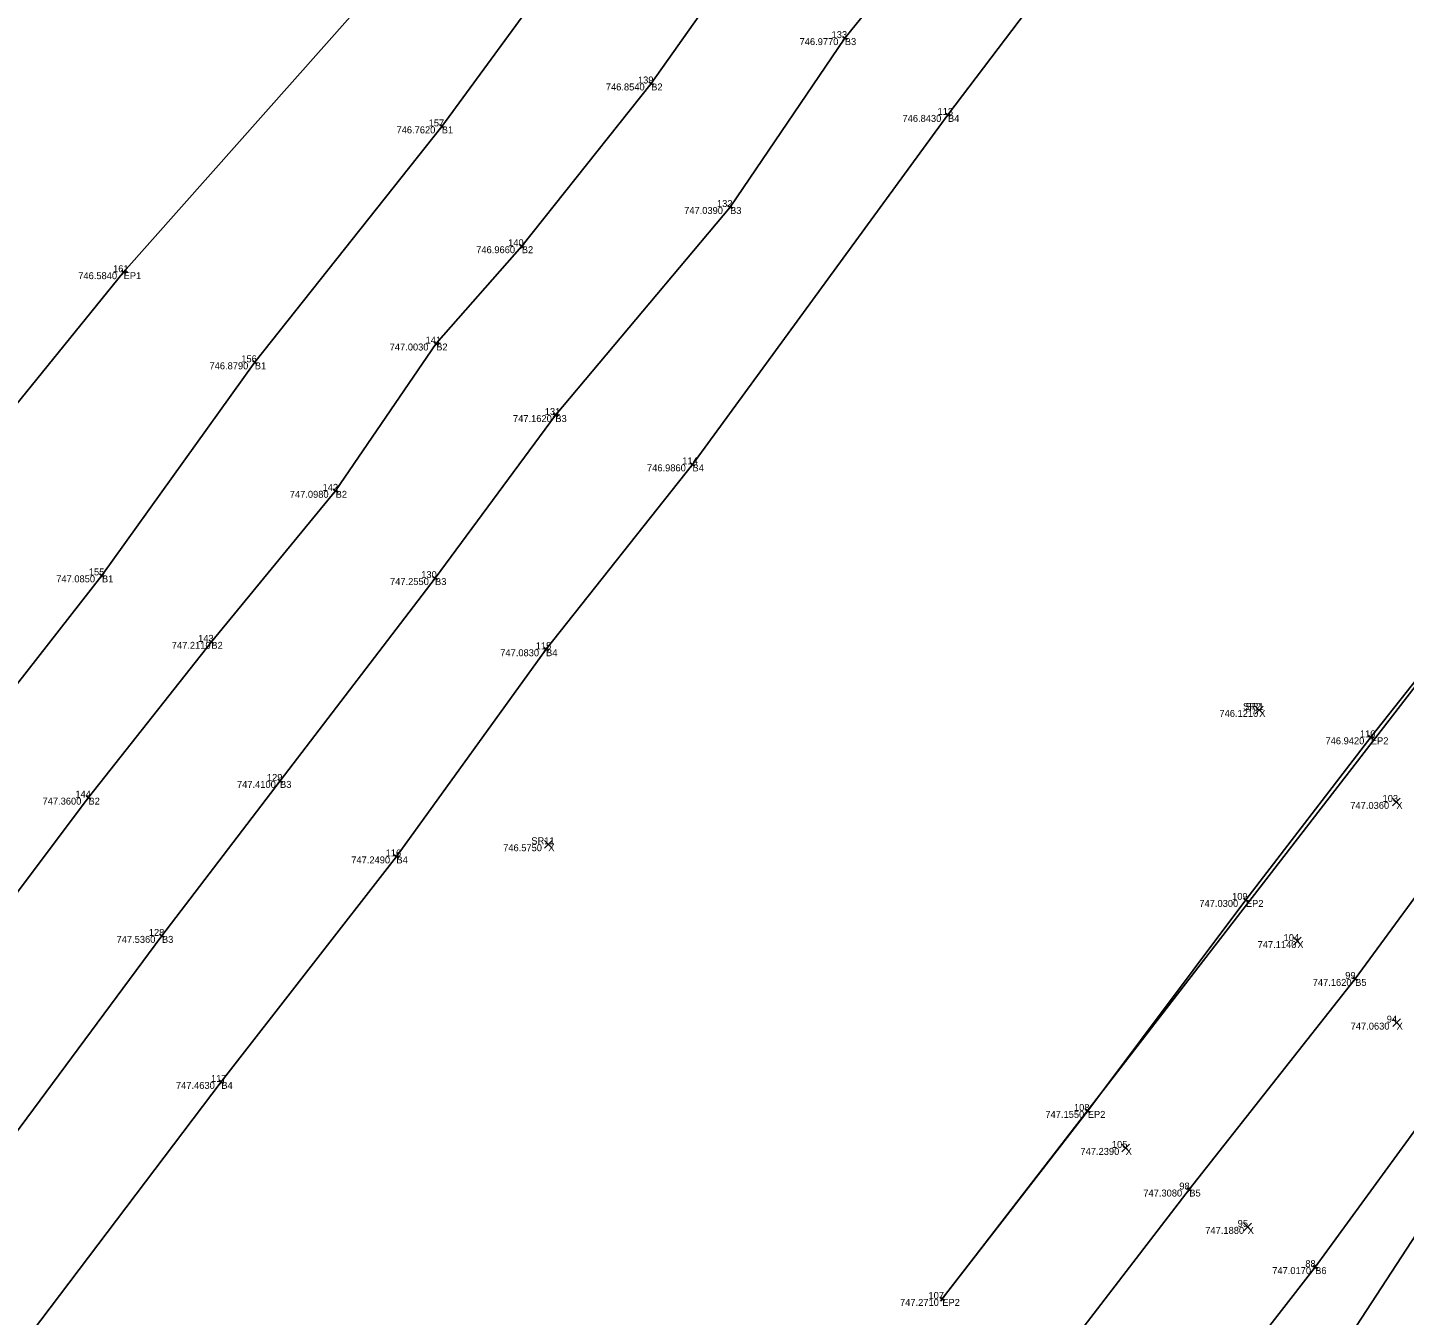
# Model space of a CAD drawing. Extents: x 1857337 to 1857837, y 693958 to 694371.
# Drawn here: x 1857604.7 to 1857723.4, y 694201.5 to 694312.5 of the extents above; entities that cross this region are included whole.
import ezdxf

# ---------------------------------------------------------------- set-up
doc = ezdxf.new("R2010")
doc.units = 0
for name, color, linetype in [('BR_X_SV_Pier_Cap_Bottom', 7, 'Continuous'), ('SV_X_Random_Point', 7, 'Continuous'), ('SV_X_Text_Comment', 7, 'Continuous'), ('SV_X_Text_Description', 7, 'Continuous'), ('SV_X_Text_Elevation', 7, 'Continuous'), ('SV_X_Text_Name', 7, 'Continuous'), ('UT_X_Electric_Cells', 7, 'Continuous')]:
    doc.layers.add(name, color=color, linetype=linetype)

msp = doc.modelspace()

# ---------------------------------------------------------------- linework, layer by layer
at = {"layer": 'BR_X_SV_Pier_Cap_Bottom'}
for p, q in [((1857675.34, 694311.45), (1857674.95, 694311.76)), ((1857675.3, 694311.8), (1857674.98, 694311.41)), ((1857675.14, 694311.61), (1857675.14, 694311.61)), ((1857658.65, 694307.55), (1857658.24, 694307.84)), ((1857658.59, 694307.9), (1857658.3, 694307.49)), ((1857658.45, 694307.7), (1857658.45, 694307.7)), ((1857684.23, 694304.84), (1857683.83, 694305.14)), ((1857684.18, 694305.19), (1857683.88, 694304.79)), ((1857684.03, 694304.99), (1857684.03, 694304.99)), ((1857640.6, 694303.85), (1857640.2, 694304.15)), ((1857640.55, 694304.2), (1857640.25, 694303.8)), ((1857640.4, 694304), (1857640.4, 694304)), ((1857665.46, 694296.91), (1857665.04, 694297.19)), ((1857665.39, 694297.26), (1857665.11, 694296.85)), ((1857665.25, 694297.05), (1857665.25, 694297.05)), ((1857647.5, 694293.51), (1857647.11, 694293.82)), ((1857647.46, 694293.86), (1857647.15, 694293.47)), ((1857647.3, 694293.67), (1857647.3, 694293.67)), ((1857613.17, 694291.26), (1857612.8, 694291.6)), ((1857613.15, 694291.62), (1857612.82, 694291.24)), ((1857612.98, 694291.43), (1857612.98, 694291.43)), ((1857640.11, 694285.11), (1857639.73, 694285.44)), ((1857640.09, 694285.47), (1857639.76, 694285.09)), ((1857639.92, 694285.28), (1857639.92, 694285.28)), ((1857624.48, 694283.51), (1857624.09, 694283.82)), ((1857624.44, 694283.86), (1857624.13, 694283.47)), ((1857624.29, 694283.66), (1857624.29, 694283.66)), ((1857650.39, 694278.95), (1857650, 694279.27)), ((1857650.35, 694279.3), (1857650.03, 694278.92)), ((1857650.19, 694279.11), (1857650.19, 694279.11)), ((1857662.21, 694274.71), (1857661.81, 694275)), ((1857662.16, 694275.06), (1857661.87, 694274.65)), ((1857662.01, 694274.86), (1857662.01, 694274.86)), ((1857631.46, 694272.44), (1857631.05, 694272.72)), ((1857631.39, 694272.79), (1857631.11, 694272.37)), ((1857631.25, 694272.58), (1857631.25, 694272.58)), ((1857611.31, 694265.14), (1857610.91, 694265.43)), ((1857611.26, 694265.49), (1857610.97, 694265.09)), ((1857611.11, 694265.29), (1857611.11, 694265.29)), ((1857640.02, 694264.91), (1857639.61, 694265.2)), ((1857639.96, 694265.26), (1857639.67, 694264.85)), ((1857639.82, 694265.06), (1857639.82, 694265.06)), ((1857620.73, 694259.4), (1857620.34, 694259.72)), ((1857620.7, 694259.76), (1857620.38, 694259.37)), ((1857620.54, 694259.56), (1857620.54, 694259.56)), ((1857649.59, 694258.76), (1857649.2, 694259.08)), ((1857649.55, 694259.12), (1857649.24, 694258.72)), ((1857649.39, 694258.92), (1857649.39, 694258.92)), ((1857720.28, 694251.49), (1857720.68, 694251.18)), ((1857720.33, 694251.13), (1857720.64, 694251.53)), ((1857720.48, 694251.33), (1857720.48, 694251.33)), ((1857626.66, 694247.41), (1857626.26, 694247.72)), ((1857626.61, 694247.76), (1857626.31, 694247.37)), ((1857626.46, 694247.57), (1857626.46, 694247.57)), ((1857610.15, 694245.98), (1857609.75, 694246.29)), ((1857610.1, 694246.33), (1857609.8, 694245.94)), ((1857609.95, 694246.13), (1857609.95, 694246.13)), ((1857636.7, 694240.92), (1857636.29, 694241.21)), ((1857636.64, 694241.27), (1857636.35, 694240.86)), ((1857636.49, 694241.06), (1857636.49, 694241.06)), ((1857709.51, 694237.46), (1857709.91, 694237.16)), ((1857709.56, 694237.11), (1857709.86, 694237.51)), ((1857709.71, 694237.31), (1857709.71, 694237.31)), ((1857616.47, 694234.06), (1857616.08, 694234.36)), ((1857616.43, 694234.41), (1857616.12, 694234.01)), ((1857616.28, 694234.21), (1857616.28, 694234.21)), ((1857719.33, 694230.35), (1857718.92, 694230.65)), ((1857719.27, 694230.7), (1857718.98, 694230.3)), ((1857719.13, 694230.5), (1857719.13, 694230.5)), ((1857621.6, 694221.46), (1857621.21, 694221.77)), ((1857621.56, 694221.82), (1857621.25, 694221.42)), ((1857621.4, 694221.62), (1857621.4, 694221.62)), ((1857695.88, 694219.27), (1857696.28, 694218.96)), ((1857695.93, 694218.92), (1857696.23, 694219.32)), ((1857696.08, 694219.12), (1857696.08, 694219.12)), ((1857705.03, 694212.19), (1857704.63, 694212.5)), ((1857704.98, 694212.54), (1857704.67, 694212.15)), ((1857704.83, 694212.34), (1857704.83, 694212.34)), ((1857715.48, 694205.8), (1857715.87, 694205.49)), ((1857715.52, 694205.45), (1857715.83, 694205.84)), ((1857715.68, 694205.65), (1857715.68, 694205.65)), ((1857683.73, 694202.76), (1857683.34, 694203.07)), ((1857683.69, 694203.11), (1857683.38, 694202.72)), ((1857683.54, 694202.91), (1857683.54, 694202.91))]:
    msp.add_line(p, q, dxfattribs=at)
at = {"layer": 'SV_X_Random_Point'}
for points in [[(1857678.61, 694370.84), (1857656.8, 694344.01), (1857632.51, 694313.44), (1857612.98, 694291.43), (1857598.98, 694274.19), (1857584.32, 694256.28)], [(1857772.28, 694315.92), (1857754.63, 694294.99), (1857737.67, 694273), (1857683.54, 694202.91), (1857696.08, 694219.12), (1857709.71, 694237.31), (1857720.48, 694251.33), (1857730.16, 694263.59)]]:
    msp.add_lwpolyline(points, dxfattribs=at)
at = {"layer": 'SV_X_Text_Elevation'}
for p, q in [((1857710.52, 694253.35), (1857711.19, 694254.02)), ((1857710.52, 694254.02), (1857711.19, 694253.35)), ((1857710.52, 694253.35), (1857711.19, 694254.02)), ((1857710.52, 694254.02), (1857711.19, 694253.35)), ((1857722.34, 694245.43), (1857723.01, 694246.09)), ((1857722.34, 694246.09), (1857723.01, 694245.43)), ((1857649.25, 694241.78), (1857649.92, 694242.44)), ((1857649.25, 694242.44), (1857649.92, 694241.78)), ((1857713.8, 694233.42), (1857714.47, 694234.09)), ((1857713.8, 694234.09), (1857714.47, 694233.42)), ((1857722.37, 694226.4), (1857723.03, 694227.07)), ((1857722.37, 694227.07), (1857723.03, 694226.4)), ((1857699.02, 694215.6), (1857699.68, 694216.26)), ((1857699.02, 694216.26), (1857699.68, 694215.6)), ((1857709.52, 694208.78), (1857710.19, 694209.45)), ((1857709.52, 694209.45), (1857710.19, 694208.78))]:
    msp.add_line(p, q, dxfattribs=at)
at = {"layer": 'UT_X_Electric_Cells'}
for points in [[(1857688.76, 694366.46), (1857664.26, 694336.58), (1857640.4, 694304), (1857624.29, 694283.66), (1857611.11, 694265.29), (1857596.56, 694246.69), (1857577.55, 694221.21), (1857552.76, 694187.23), (1857529.48, 694157.73), (1857506.44, 694129.2)], [(1857700.07, 694362.04), (1857689.25, 694348.99), (1857682.84, 694339.86), (1857667.65, 694320.73), (1857658.45, 694307.7), (1857647.3, 694293.67), (1857639.92, 694285.28), (1857631.25, 694272.58), (1857620.54, 694259.56), (1857609.95, 694246.13), (1857585.77, 694213.92), (1857569.94, 694193.46), (1857560.42, 694180.39), (1857538.66, 694151.42), (1857515.13, 694123.12)], [(1857711.16, 694357.22), (1857703.2, 694345.96), (1857690.71, 694330.85), (1857675.14, 694311.61), (1857665.25, 694297.05), (1857650.19, 694279.11), (1857639.82, 694265.06), (1857626.46, 694247.57), (1857616.28, 694234.21), (1857602.42, 694215.52), (1857593.56, 694204.62), (1857579.14, 694185.2), (1857570.86, 694174.07), (1857548.44, 694145.75), (1857525.39, 694115.5)], [(1857720.32, 694352.91), (1857704.98, 694332.67), (1857684.03, 694304.99), (1857662.01, 694274.86), (1857649.39, 694258.92), (1857636.49, 694241.06), (1857621.4, 694221.62), (1857600.9, 694194.58), (1857569.51, 694153.93), (1857555.9, 694136.99), (1857538.65, 694113.77)], [(1857781.43, 694311.93), (1857762.2, 694286.33), (1857747.53, 694267.73), (1857737.36, 694255.21), (1857727.43, 694241.82), (1857719.13, 694230.5), (1857704.83, 694212.34), (1857686.36, 694188.29)], [(1857789.96, 694304.6), (1857771.69, 694278.3), (1857757.22, 694258.85), (1857703.3, 694176.12), (1857697.07, 694181.68), (1857715.68, 694205.65), (1857728.74, 694223.57), (1857737.21, 694233.91), (1857746.66, 694246.32)]]:
    msp.add_lwpolyline(points, dxfattribs=at)

# ---------------------------------------------------------------- texts
at = {"layer": 'SV_X_Text_Comment'}
for s, p in [('B3', (1857675.14, 694311.01)), ('B2', (1857658.45, 694307.1)), ('B4', (1857684.03, 694304.39)), ('B1', (1857640.4, 694303.4)), ('B3', (1857665.25, 694296.45)), ('B2', (1857647.3, 694293.07)), ('EP1', (1857612.98, 694290.83)), ('B2', (1857639.92, 694284.68)), ('B1', (1857624.29, 694283.06)), ('B3', (1857650.19, 694278.51)), ('B4', (1857662.01, 694274.26)), ('B2', (1857631.25, 694271.98)), ('B1', (1857611.11, 694264.69)), ('B3', (1857639.82, 694264.46)), ('B2', (1857620.54, 694258.96)), ('B4', (1857649.39, 694258.32)), ('X', (1857710.86, 694253.09)), ('X', (1857710.86, 694253.09)), ('EP2', (1857720.48, 694250.73)), ('B3', (1857626.46, 694246.97)), ('B2', (1857609.95, 694245.53)), ('X', (1857722.68, 694245.16)), ('X', (1857649.58, 694241.51)), ('B4', (1857636.49, 694240.46)), ('EP2', (1857709.71, 694236.71)), ('B3', (1857616.28, 694233.61)), ('X', (1857714.14, 694233.16)), ('B5', (1857719.13, 694229.9)), ('X', (1857722.7, 694226.13)), ('B4', (1857621.4, 694221.02)), ('EP2', (1857696.08, 694218.52)), ('X', (1857699.35, 694215.33)), ('B5', (1857704.83, 694211.74)), ('X', (1857709.86, 694208.52)), ('B6', (1857715.68, 694205.05)), ('EP2', (1857683.54, 694202.31))]:
    msp.add_text(s, height=0.6, dxfattribs=at).set_placement(p)
at = {"layer": 'SV_X_Text_Description'}
for s, p in [('746.9770', (1857671.24, 694311.01)), ('746.8540', (1857654.54, 694307.1)), ('746.8430', (1857680.11, 694304.39)), ('746.7620', (1857636.5, 694303.4)), ('747.0390', (1857661.29, 694296.45)), ('746.9660', (1857643.37, 694293.07)), ('746.5840', (1857609.07, 694290.83)), ('747.0030', (1857635.91, 694284.68)), ('746.8790', (1857620.38, 694283.06)), ('747.1620', (1857646.54, 694278.51)), ('746.9860', (1857658.09, 694274.26)), ('747.0980', (1857627.3, 694271.98)), ('747.0850', (1857607.17, 694264.69)), ('747.2550', (1857635.94, 694264.46)), ('747.2110', (1857617.13, 694258.96)), ('747.0830', (1857645.44, 694258.32)), ('746.1210', (1857707.43, 694253.09)), ('746.1210', (1857707.43, 694253.09)), ('746.9420', (1857716.57, 694250.73)), ('747.4100', (1857622.75, 694246.97)), ('747.3600', (1857605.99, 694245.53)), ('747.0360', (1857718.71, 694245.16)), ('746.5750', (1857645.69, 694241.51)), ('747.2490', (1857632.6, 694240.46)), ('747.0300', (1857705.7, 694236.71)), ('747.5360', (1857612.37, 694233.61)), ('747.1140', (1857710.72, 694233.16)), ('747.1620', (1857715.47, 694229.9)), ('747.0630', (1857718.74, 694226.13)), ('747.4630', (1857617.49, 694221.02)), ('747.1550', (1857692.43, 694218.52)), ('747.2390', (1857695.45, 694215.33)), ('747.3080', (1857700.87, 694211.74)), ('747.1880', (1857706.21, 694208.52)), ('747.0170', (1857711.98, 694205.05)), ('747.2710', (1857679.9, 694202.31))]:
    msp.add_text(s, height=0.6, dxfattribs=at).set_placement(p)
at = {"layer": 'SV_X_Text_Name'}
for s, p in [('133', (1857674, 694311.61)), ('139', (1857657.31, 694307.7)), ('157', (1857639.27, 694304)), ('113', (1857683.13, 694304.99)), ('132', (1857664.12, 694297.05)), ('140', (1857646.12, 694293.67)), ('161', (1857612.07, 694291.43)), ('141', (1857639.01, 694285.28)), ('156', (1857623.12, 694283.66)), ('131', (1857649.28, 694279.11)), ('114', (1857661.13, 694274.86)), ('142', (1857630.13, 694272.58)), ('155', (1857609.98, 694265.29)), ('130', (1857638.63, 694265.06)), ('143', (1857619.4, 694259.56)), ('115', (1857648.5, 694258.92)), ('SR2', (1857709.46, 694253.69)), ('SR1', (1857709.68, 694253.69)), ('110', (1857719.54, 694251.33)), ('129', (1857625.33, 694247.57)), ('144', (1857608.82, 694246.13)), ('103', (1857721.49, 694245.76)), ('116', (1857635.56, 694241.06)), ('SR11', (1857648.12, 694242.11)), ('109', (1857708.52, 694237.31)), ('128', (1857615.15, 694234.21)), ('104', (1857712.96, 694233.76)), ('99', (1857718.27, 694230.5)), ('94', (1857721.85, 694226.73)), ('117', (1857620.51, 694221.62)), ('108', (1857694.89, 694219.12)), ('105', (1857698.16, 694215.93)), ('98', (1857703.97, 694212.34)), ('95', (1857709, 694209.12)), ('88', (1857714.83, 694205.65)), ('107', (1857682.35, 694202.91))]:
    msp.add_text(s, height=0.6, dxfattribs=at).set_placement(p)

doc.saveas('drawing.dxf')
